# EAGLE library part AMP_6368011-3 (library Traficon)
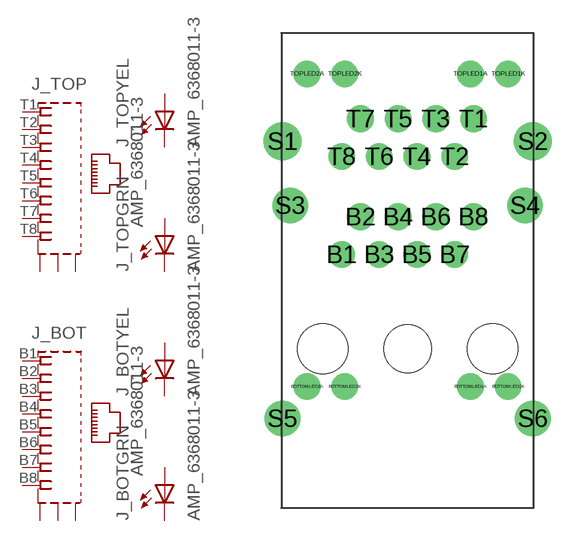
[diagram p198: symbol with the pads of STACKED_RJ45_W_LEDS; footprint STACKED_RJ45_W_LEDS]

Designator prefix J; gates _TOP=JACK8SH_3PE _BOT=JACK8SH_3PE _TOPYEL=LED _TOPGRN=LED _BOTYEL=LED _BOTGRN=LED

## AMP_6368011-3  [STACKED_RJ45_W_LEDS]
B1  _BOT:1  pas
B2  _BOT:2  pas
B3  _BOT:3  pas
B4  _BOT:4  pas
B5  _BOT:5  pas
B6  _BOT:6  pas
B7  _BOT:7  pas
B8  _BOT:8  pas
BOTTOMLED1A  _BOTYEL:A  pas
BOTTOMLED1K  _BOTYEL:C  pas
BOTTOMLED2A  _BOTGRN:A  pas
BOTTOMLED2K  _BOTGRN:C  pas
S1  _BOT:S1  pas
S2  _BOT:S2  pas
S3  _BOT:S3  pas
S4  _TOP:S1  pas
S5  _TOP:S2  pas
S6  _TOP:S3  pas
T1  _TOP:1  pas
T2  _TOP:2  pas
T3  _TOP:3  pas
T4  _TOP:4  pas
T5  _TOP:5  pas
T6  _TOP:6  pas
T7  _TOP:7  pas
T8  _TOP:8  pas
TOPLED1A  _TOPYEL:A  pas
TOPLED1K  _TOPYEL:C  pas
TOPLED2A  _TOPGRN:A  pas
TOPLED2K  _TOPGRN:C  pas

## Footprint STACKED_RJ45_W_LEDS (pad centres in mm)
CT: 24/10/2008: added central hole for compatibility with RIA-XMultiple-Pulse second sources.
drill 1.2 round: B1 1.265,6.35; B2 2.535,8.89; B3 3.805,6.35; B4 5.075,8.89; B5 6.345,6.35; B6 7.615,8.89; B7 8.885,6.35; B8 10.155,8.89; BOTTOMLED1A 9.95,-2.54; BOTTOMLED1K 12.49,-2.54; BOTTOMLED2A -1.06,-2.54; BOTTOMLED2K 1.48,-2.54; T1 10.155,15.49; T2 8.885,12.95; T3 7.615,15.49; T4 6.345,12.95; T5 5.075,15.49; T6 3.805,12.95; T7 2.535,15.49; T8 1.265,12.95; TOPLED1A 9.95,18.51; TOPLED1K 12.49,18.51; TOPLED2A -1.06,18.51; TOPLED2K 1.48,18.51
drill 1.7 round: S1 -2.72,13.971; S2 14.15,13.971
drill 1.6 round: S3 -2.2,9.65; S4 13.63,9.65; S5 -2.72,-4.698; S6 14.15,-4.698
hole 3.4 at 0,0
hole 3.4 at 11.43,0
hole 3.2 at 5.71,0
